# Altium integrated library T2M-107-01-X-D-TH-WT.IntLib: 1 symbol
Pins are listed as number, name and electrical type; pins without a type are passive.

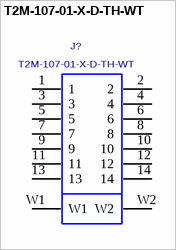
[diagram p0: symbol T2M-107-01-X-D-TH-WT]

## T2M-107-01-X-D-TH-WT
designator J?
2MM PITCH SHROUDED TERMINAL STRIP, 14 PINS.; MANUFACTURER: SAMTEC
footprint T2M-107-01-X-D-TH-WT
pins: 1, 2, 3, 4, 5, 6, 7, 8, 9, 10, 11, 12, 13, 14, W1, W2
